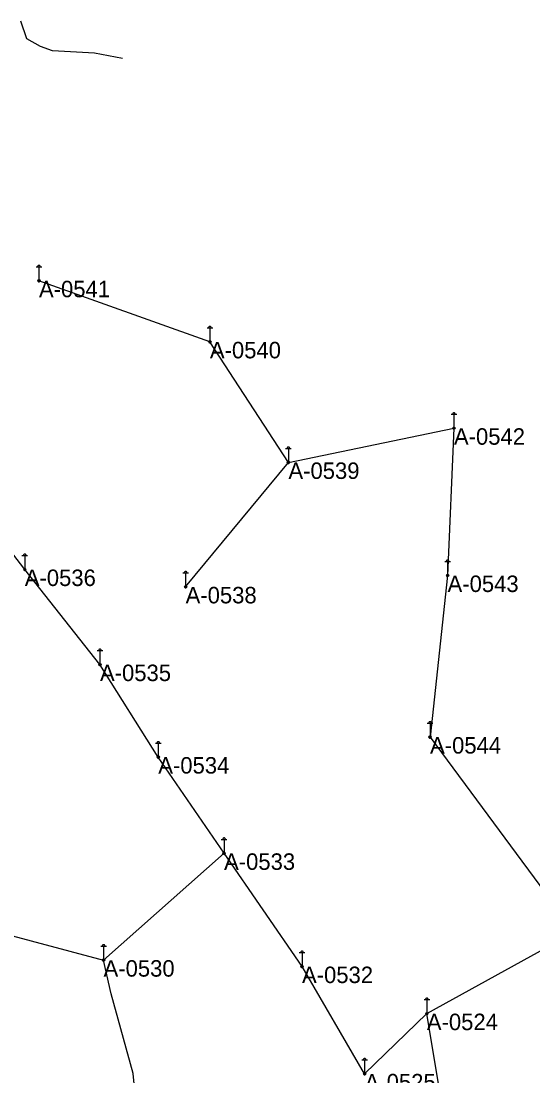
# Model space of a CAD drawing. Extents: x -729889 to -691139, y -995431 to -974354.
# Drawn here: x -725684.3 to -725591.1, y -977808.4 to -977616.3 of the extents above; entities that cross this region are included whole.
import ezdxf

# ---------------------------------------------------------------- set-up
doc = ezdxf.new("R2010")
doc.units = 0
for name, color, linetype in [('Atributy', 7, 'Continuous'), ('Kabel napájecí ze systému VO', 7, 'Continuous'), ('Kabelové vedení VO', 7, 'Continuous'), ('Světelný bod na stožáru sadovém', 7, 'Continuous')]:
    doc.layers.add(name, color=color, linetype=linetype)

# ---------------------------------------------------------------- blocks, each defined once
blk = doc.blocks.new('6.571')
at = {"layer": 'Světelný bod na stožáru sadovém'}
for p, q in [((-0.51, 2.54), (0.51, 2.54)), ((0, 2.54), (0, 0.2))]:
    blk.add_line(p, q, dxfattribs=at)
for points in [[(0.25, 2.54), (0.25, 2.56), (0.25, 2.58), (0.24, 2.6), (0.24, 2.62), (0.23, 2.64), (0.22, 2.66), (0.21, 2.69), (0.19, 2.7), (0.18, 2.72), (0.16, 2.73), (0.15, 2.75), (0.13, 2.76), (0.11, 2.77), (0.09, 2.78), (0.07, 2.78), (0.05, 2.79), (0.02, 2.79), (0, 2.79), (-0.02, 2.79), (-0.05, 2.79), (-0.07, 2.78), (-0.09, 2.78), (-0.11, 2.77), (-0.13, 2.76), (-0.15, 2.75), (-0.16, 2.73), (-0.18, 2.72), (-0.19, 2.7), (-0.21, 2.69), (-0.22, 2.66), (-0.23, 2.64), (-0.24, 2.62), (-0.24, 2.6), (-0.25, 2.58), (-0.25, 2.56), (-0.25, 2.54)], [(-0.2, 0), (-0.17, -0.1), (-0.08, -0.18), (0.04, -0.19), (0.13, -0.14), (0.19, -0.05), (0.18, 0.07), (0.12, 0.15), (0.02, 0.19), (-0.09, 0.17), (-0.17, 0.09), (-0.18, -0.01), (-0.15, -0.1), (-0.06, -0.17), (0.04, -0.17), (0.12, -0.12), (0.17, -0.03), (0.16, 0.08), (0.1, 0.14), (0.01, 0.17), (-0.09, 0.14), (-0.15, 0.07), (-0.16, -0.01), (-0.12, -0.1), (-0.04, -0.15), (0.04, -0.15), (0.12, -0.1), (0.15, -0.01), (0.14, 0.07), (0.08, 0.13), (-0.01, 0.15), (-0.09, 0.12), (-0.13, 0.06), (-0.14, -0.02), (-0.1, -0.1), (-0.03, -0.13), (0.04, -0.13), (0.11, -0.08), (0.13, 0), (0.12, 0.07), (0.06, 0.12), (-0.02, 0.13), (-0.08, 0.1), (-0.12, 0.05), (-0.12, -0.03), (-0.08, -0.09), (-0.02, -0.11), (0.05, -0.11), (0.1, -0.06), (0.11, 0.01), (0.1, 0.06), (0.05, 0.11), (-0.02, 0.11), (-0.07, 0.09), (-0.1, 0.04), (-0.1, -0.03), (-0.06, -0.08), (-0.02, -0.1), (0.05, -0.08), (0.09, -0.04), (0.1, 0.01), (0.08, 0.06), (0.03, 0.09), (-0.02, 0.09), (-0.06, 0.07), (-0.08, 0.02), (-0.08, -0.03), (-0.05, -0.06), (-0.01, -0.08), (0.04, -0.06), (0.07, -0.03), (0.07, 0.01), (0.06, 0.05), (0.02, 0.07), (-0.02, 0.07), (-0.05, 0.05), (-0.07, 0.02), (-0.06, -0.03), (-0.04, -0.05), (0, -0.06), (0.04, -0.04), (0.05, -0.02), (0.06, 0.01), (0.04, 0.04), (0.01, 0.05), (-0.02, 0.05), (-0.04, 0.04), (-0.05, 0.01), (-0.04, -0.02), (-0.02, -0.03), (0.01, -0.04), (0.03, -0.03), (0.04, -0.01), (0.04, 0.01), (0.02, 0.03), (0.01, 0.04), (-0.01, 0.03), (-0.02, 0.02), (-0.03, 0.01), (-0.02, -0.01), (-0.01, -0.02)], [(-0.01, -0.02), (0.01, -0.02), (0.01, -0.01), (0.02, 0), (0.02, 0.01), (0.01, 0.02), (0, 0.02), (-0.01, 0.01), (-0.01, 0.01), (-0.01, 0.01)]]:
    blk.add_lwpolyline(points, dxfattribs=at)
blk.add_circle((0, 0), 0.203, dxfattribs=at)

msp = doc.modelspace()

# ---------------------------------------------------------------- linework, layer by layer
at = {"layer": 'Kabel napájecí ze systému VO'}
msp.add_lwpolyline([(-725665.81, -977623.07), (-725670.9, -977622.11), (-725678.52, -977621.72), (-725680.76, -977620.91), (-725683.22, -977619.54), (-725684.3, -977616.28)], dxfattribs=at)
at = {"layer": 'Kabelové vedení VO'}
for p, q in [((-725649.89, -977674.68), (-725681.01, -977663.56)), ((-725635.59, -977696.64), (-725649.89, -977674.68)), ((-725635.59, -977696.64), (-725605.46, -977690.41)), ((-725605.46, -977690.41), (-725606.62, -977717.23)), ((-725683.59, -977716.14), (-725698.35, -977696.93)), ((-725654.31, -977719.3), (-725635.59, -977696.64)), ((-725669.9, -977733.45), (-725683.59, -977716.14)), ((-725606.62, -977717.23), (-725609.81, -977746.65)), ((-725659.29, -977750.29), (-725669.9, -977733.45)), ((-725609.81, -977746.65), (-725583.57, -977782.17)), ((-725647.31, -977767.82), (-725659.29, -977750.29)), ((-725669.25, -977787.27), (-725647.31, -977767.82)), ((-725633.12, -977788.44), (-725647.31, -977767.82)), ((-725703.89, -977778.04), (-725669.25, -977787.27)), ((-725610.39, -977797.01), (-725583.57, -977782.17)), ((-725621.72, -977807.98), (-725633.12, -977788.44)), ((-725610.39, -977797.01), (-725621.72, -977807.98)), ((-725606.47, -977820.43), (-725610.39, -977797.01))]:
    msp.add_line(p, q, dxfattribs=at)
msp.add_lwpolyline([(-725690.7, -977832.72), (-725688.89, -977830.7), (-725682.01, -977825.67), (-725670.24, -977817.6), (-725663.36, -977812.84), (-725663.89, -977807.94), (-725667.86, -977793.39), (-725669.25, -977787.27)], dxfattribs=at)

# ---------------------------------------------------------------- block references
at = {"layer": 'Světelný bod na stožáru sadovém', "xscale": 1.0016949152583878, "yscale": 1.0016949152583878}
for p in [(-725681.01, -977663.56), (-725649.89, -977674.68), (-725605.46, -977690.41), (-725635.59, -977696.64), (-725683.59, -977716.14), (-725606.62, -977717.23), (-725654.31, -977719.3), (-725669.9, -977733.45), (-725609.81, -977746.65), (-725659.29, -977750.29), (-725647.31, -977767.82), (-725669.25, -977787.27), (-725633.12, -977788.44), (-725610.39, -977797.01), (-725621.72, -977807.98)]:
    msp.add_blockref('6.571', p, dxfattribs=at)

# ---------------------------------------------------------------- texts
at = {"layer": 'Atributy'}
for s, p in [('A-0541', (-725681.01, -977666.57)), ('A-0540', (-725649.89, -977677.69)), ('A-0542', (-725605.46, -977693.42)), ('A-0539', (-725635.59, -977699.65)), ('A-0536', (-725683.59, -977719.15)), ('A-0543', (-725606.62, -977720.24)), ('A-0538', (-725654.31, -977722.31)), ('A-0535', (-725669.9, -977736.46)), ('A-0544', (-725609.81, -977749.66)), ('A-0534', (-725659.29, -977753.3)), ('A-0533', (-725647.31, -977770.83)), ('A-0530', (-725669.25, -977790.28)), ('A-0532', (-725633.12, -977791.45)), ('A-0524', (-725610.39, -977800.02)), ('A-0525', (-725621.72, -977810.99))]:
    msp.add_text(s, height=3, dxfattribs=at).set_placement(p)

doc.saveas('drawing.dxf')
